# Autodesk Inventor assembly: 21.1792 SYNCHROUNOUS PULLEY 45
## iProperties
Created: 2007-05
Part Number: 21.1792 SYNCHROUNOUS PULLEY 45
Document SubType Name: Assembly
Designer: Andy Moles
Author: Andy Moles
